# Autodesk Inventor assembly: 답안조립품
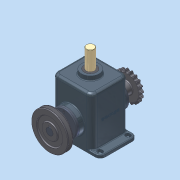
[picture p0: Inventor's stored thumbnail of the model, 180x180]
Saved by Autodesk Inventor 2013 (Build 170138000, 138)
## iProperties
Created: 2015-03
Part Number: 답안조립품
Document SubType Name: Assembly
Designer: Administrator
Author: Administrator
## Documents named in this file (15)
- C:\Users\Administrator\Desktop\350306V1001\답안조립품.iam
- C:\Users\Administrator\Desktop\350306V1001\본체.ipt
- C:\Users\Administrator\Desktop\350306V1001\M4x0.5.ipt
- C:\Users\Administrator\Desktop\350306V1001\V-벨트풀리.ipt
- C:\Users\Administrator\Desktop\350306V1001\가변스프링.ipt
- C:\Users\Administrator\Desktop\350306V1001\멈춤나사 M5x0.5.ipt
- C:\Users\Administrator\Desktop\350306V1001\멈춤링.ipt
- C:\Users\Administrator\Desktop\350306V1001\베어링 6205.ipt
- C:\Users\Administrator\Desktop\350306V1001\부시.ipt
- C:\Users\Administrator\Desktop\350306V1001\슬라이드.ipt
- C:\Users\Administrator\Desktop\350306V1001\오일실.ipt
- C:\Users\Administrator\Desktop\350306V1001\체인 스프로킷.ipt
- C:\Users\Administrator\Desktop\350306V1001\커버.ipt
- C:\Users\Administrator\Desktop\350306V1001\키 8x8.ipt
- C:\Users\Administrator\Desktop\350306V1001\편심축.ipt
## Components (9 placed, 4 different names)
1. V-벨트풀리:1 — 플러쉬:3
2. 가변스프링:1
3. 5-체인 스프로킷:1 — 플러쉬:2
4. M4x0.5:1
5. M4x0.5:3
6. M4x0.5:4
7. M4x0.5:2
8. M4x0.5:5
9. M4x0.5:6
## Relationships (2: Flush 2)
- 플러쉬:2 [Flush]: 5-체인 스프로킷:1
- 플러쉬:3 [Flush]: V-벨트풀리:1
